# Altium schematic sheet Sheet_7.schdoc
size 444 x 280 mm
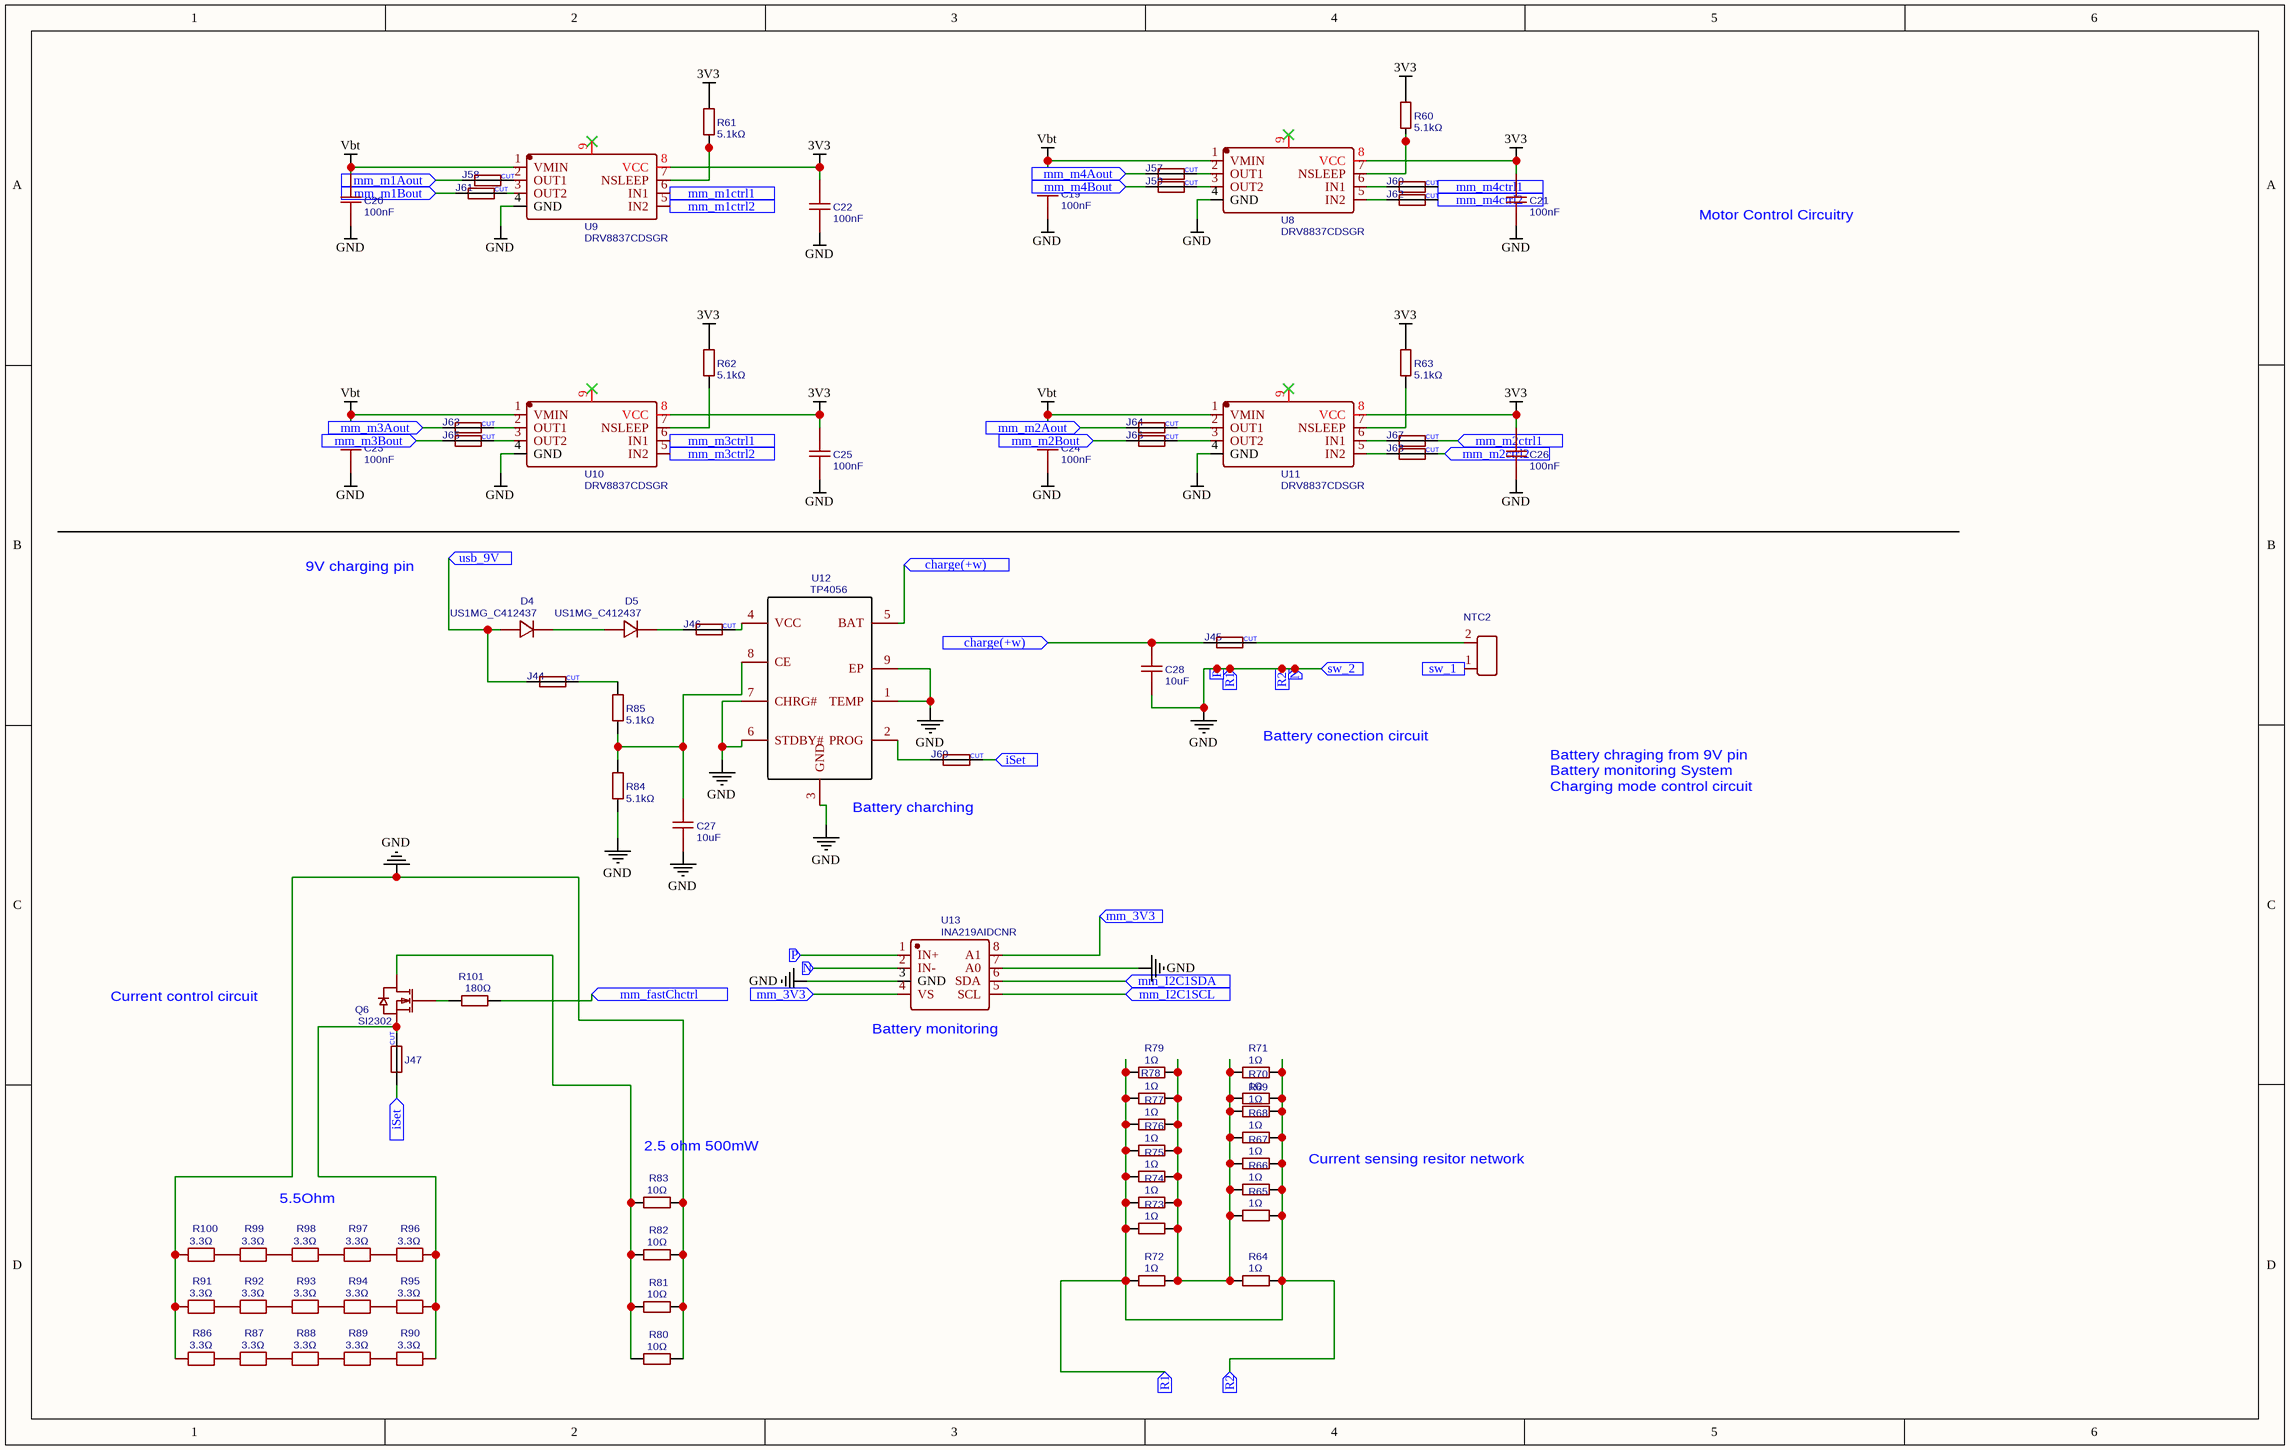
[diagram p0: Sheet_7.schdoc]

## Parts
C19  100nF  [C0805]
C20  100nF  [C0805]
C21  100nF  [C0805]
C22  100nF  [C0805]
C23  100nF  [C0805]
C24  100nF  [C0805]
C25  100nF  [C0805]
C26  100nF  [C0805]
C27  10uF  [C0805]
C28  10uF  [C0805]
D4  US1MG_C412437  [SMA_L4.4-W2.8-LS5.4-RD]
D5  US1MG_C412437  [SMA_L4.4-W2.8-LS5.4-RD]
J44  0603  [JMP-0603-CUTTABLE]  (value not drawn)
J45  0603  [JMP-0603-CUTTABLE]  (value not drawn)
J46  0603  [JMP-0603-CUTTABLE]  (value not drawn)
J47  0603  [JMP-0603-CUTTABLE]  (value not drawn)
J57  0603  [JMP-0603-CUTTABLE]  (value not drawn)
J58  0603  [JMP-0603-CUTTABLE]  (value not drawn)
J59  0603  [JMP-0603-CUTTABLE]  (value not drawn)
J60  0603  [JMP-0603-CUTTABLE]  (value not drawn)
J61  0603  [JMP-0603-CUTTABLE]  (value not drawn)
J62  0603  [JMP-0603-CUTTABLE]  (value not drawn)
J63  0603  [JMP-0603-CUTTABLE]  (value not drawn)
J64  0603  [JMP-0603-CUTTABLE]  (value not drawn)
J65  0603  [JMP-0603-CUTTABLE]  (value not drawn)
J66  0603  [JMP-0603-CUTTABLE]  (value not drawn)
J67  0603  [JMP-0603-CUTTABLE]  (value not drawn)
J68  0603  [JMP-0603-CUTTABLE]  (value not drawn)
J69  0603  [JMP-0603-CUTTABLE]  (value not drawn)
NTC2  NTC/10k  [2PIN_2.54_MM_JST_XHP_JST_CONNECTOR 1]  (value not drawn)
Q6  SI2302  [SOT-23-3_L2.9-W1.3-P1.90-LS2.4-BR]
R60  5.1kΩ  [R0805]
R61  5.1kΩ  [R0805]
R62  5.1kΩ  [R0805]
R63  5.1kΩ  [R0805]
R64  1Ω  [R0402]
R65  1Ω  [R0402]
R66  1Ω  [R0402]
R67  1Ω  [R0402]
R68  1Ω  [R0402]
R69  1Ω  [R0402]
R70  1Ω  [R0402]
R71  1Ω  [R0402]
R72  1Ω  [R0402]
R73  1Ω  [R0402]
R74  1Ω  [R0402]
R75  1Ω  [R0402]
R76  1Ω  [R0402]
R77  1Ω  [R0402]
R78  1Ω  [R0402]
R79  1Ω  [R0402]
R80  10Ω  [R0805_NEW]
R81  10Ω  [R0805_NEW]
R82  10Ω  [R0805_NEW]
R83  10Ω  [R0805_NEW]
R84  5.1kΩ  [R0805]
R85  5.1kΩ  [R0805]
R86  3.3Ω  [R0603]
R87  3.3Ω  [R0603]
R88  3.3Ω  [R0603]
R89  3.3Ω  [R0603]
R90  3.3Ω  [R0603]
R91  3.3Ω  [R0603]
R92  3.3Ω  [R0603]
R93  3.3Ω  [R0603]
R94  3.3Ω  [R0603]
R95  3.3Ω  [R0603]
R96  3.3Ω  [R0603]
R97  3.3Ω  [R0603]
R98  3.3Ω  [R0603]
R99  3.3Ω  [R0603]
R100  3.3Ω  [R0603]
R101  180Ω  [R0805]
U8  DRV8837CDSGR  [WSON-8_L2.0-W2.0-P0.50-TL-EP]
U9  DRV8837CDSGR  [WSON-8_L2.0-W2.0-P0.50-TL-EP]
U10  DRV8837CDSGR  [WSON-8_L2.0-W2.0-P0.50-TL-EP]
U11  DRV8837CDSGR  [WSON-8_L2.0-W2.0-P0.50-TL-EP]
U12  TP4056  [ESOP-8_L4.9-W3.9-P1.27-LS6.0-BL-EP]
U13  INA219AIDCNR  [SOT-23-8_L3.0-W1.7-P0.65-LS2.8-BR]

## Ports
charge(+w) (in), iSet (in), mm_3V3 (in), mm_fastChctrl (in), mm_I2C1SCL (in), mm_I2C1SDA (in), mm_m1Aout (in), mm_m1Bout (in), mm_m1ctrl1 (in), mm_m1ctrl2 (in), mm_m2Aout (in), mm_m2Bout (in), mm_m2ctrl1 (in), mm_m2ctrl2 (in), mm_m3Aout (in), mm_m3Bout (in), mm_m3ctrl1 (in), mm_m3ctrl2 (in), mm_m4Aout (in), mm_m4Bout (in), mm_m4ctrl1 (in), mm_m4ctrl2 (in), N (in), P (in), R1 (in), R2 (in), sw_1 (in), sw_2 (in), usb_9V (in)

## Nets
3V3: C21.1 C22.1 C25.1 C26.1 R60.1 R61.1 R62.1 R63.1 U8.8(VCC) U9.8(VCC) U10.8(VCC) U11.8(VCC)
GND: C19.2 C20.2 C21.2 C22.2 C23.2 C24.2 C25.2 C26.2 C27.2 C28.2 R64.2 R65.2 R66.2 R67.2 R68.2 R69.2 R70.2 R71.2 R72.1 R73.1 R74.1 R75.1 R76.1 R77.1 R78.1 R79.1 R80.2 R81.2 R82.2 R83.2 R84.2 R86.1 R91.1 R100.1 U8.4(GND) U9.4(GND) U10.4(GND) U11.4(GND) U12.1(TEMP) U12.3(GND) U12.6(STDBY#) U12.7(CHRG#) U12.9(EP) U13.1(IN+) U13.2(IN-) U13.3(GND) U13.7(A0) ; port sw_2, port R2, port R1, port N, port P
Vbt: C19.1 C20.1 C23.1 C24.1 U8.1(VMIN) U9.1(VMIN) U10.1(VMIN) U11.1(VMIN)
charge(+w): C28.1 J45.2 U12.5(BAT) ; port charge(+w)
iSet: J47.2 J69.1 ; port iSet
mm_3V3: U13.4(VS) U13.8(A1) ; port mm_3V3
mm_fastChctrl: R101.2 ; port mm_fastChctrl
mm_I2C1SCL: U13.5(SCL) ; port mm_I2C1SCL
mm_I2C1SDA: U13.6(SDA) ; port mm_I2C1SDA
mm_m1Aout: J58.2 ; port mm_m1Aout
mm_m1Bout: J61.2 ; port mm_m1Bout
mm_m1ctrl1: U9.6(IN1) ; port mm_m1ctrl1
mm_m1ctrl2: U9.5(IN2) ; port mm_m1ctrl2
mm_m2Aout: J64.2 ; port mm_m2Aout
mm_m2Bout: J66.2 ; port mm_m2Bout
mm_m2ctrl1: J67.1 ; port mm_m2ctrl1
mm_m2ctrl2: J68.1 ; port mm_m2ctrl2
mm_m3Aout: J63.2 ; port mm_m3Aout
mm_m3Bout: J65.2 ; port mm_m3Bout
mm_m3ctrl1: U10.6(IN1) ; port mm_m3ctrl1
mm_m3ctrl2: U10.5(IN2) ; port mm_m3ctrl2
mm_m4Aout: J57.2 ; port mm_m4Aout
mm_m4Bout: J59.2 ; port mm_m4Bout
mm_m4ctrl1: J60.1 ; port mm_m4ctrl1
mm_m4ctrl2: J62.1 ; port mm_m4ctrl2
sw_1: NTC2.1 ; port sw_1
usb_9V: D4.2(A) J44.2 ; port usb_9V
NetC27_1: C27.1 R84.1 R85.2 U12.8(CE)
NetD4_1: D4.1(C) D5.2(A)
NetD5_1: D5.1(C) J46.2
NetJ44_1: J44.1 R85.1
NetJ45_1: J45.1 NTC2.2
NetJ46_1: J46.1 U12.4(VCC)
NetJ47_1: J47.1 Q6.2(S) R90.2 R95.2 R96.2
NetJ57_1: J57.1 U8.2(OUT1)
NetJ58_1: J58.1 U9.2(OUT1)
NetJ59_1: J59.1 U8.3(OUT2)
NetJ60_2: J60.2 U8.6(IN1)
NetJ61_1: J61.1 U9.3(OUT2)
NetJ62_2: J62.2 U8.5(IN2)
NetJ63_1: J63.1 U10.2(OUT1)
NetJ64_1: J64.1 U11.2(OUT1)
NetJ65_1: J65.1 U10.3(OUT2)
NetJ66_1: J66.1 U11.3(OUT2)
NetJ67_2: J67.2 U11.6(IN1)
NetJ68_2: J68.2 U11.5(IN2)
NetJ69_2: J69.2 U12.2(PROG)
NetQ6_1: Q6.1(G) R101.1
NetQ6_3: Q6.3(D) R80.1 R81.1 R82.1 R83.1
NetR60_2: R60.2 U8.7(NSLEEP)
NetR61_2: R61.2 U9.7(NSLEEP)
NetR62_2: R62.2 U10.7(NSLEEP)
NetR63_2: R63.2 U11.7(NSLEEP)
NetR64_1: R64.1 R65.1 R66.1 R67.1 R68.1 R69.1 R70.1 R71.1 R72.2 R73.2 R74.2 R75.2 R76.2 R77.2 R78.2 R79.2
NetR86_2: R86.2 R87.1
NetR87_2: R87.2 R88.1
NetR88_2: R88.2 R89.1
NetR89_2: R89.2 R90.1
NetR91_2: R91.2 R92.1
NetR92_2: R92.2 R93.1
NetR93_2: R93.2 R94.1
NetR94_2: R94.2 R95.1
NetR96_1: R96.1 R97.2
NetR97_1: R97.1 R98.2
NetR98_1: R98.1 R99.2
NetR99_1: R99.1 R100.2

Not connected (* = marked no-connect by the designer): U8 9(PAD)*; U9 9(PAD)*; U10 9(PAD)*; U11 9(PAD)*

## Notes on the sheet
- Motor Control Circuitry
- 9V charging pin
- Battery conection circuit
- Battery chraging from 9V pin
  Battery monitoring System
  Charging mode control circuit
- (near U12) Battery charching
- Current control circuit
- (near U13) Battery monitoring
- 5.5Ohm
- (near R83) 2.5 ohm 500mW
- Current sensing resitor network

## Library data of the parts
C19-C26 = 100nF: Manufacturer Part: CC0805KRX7R9BB104; Manufacturer: YAGEO(国巨); nameAlias: Value
C27 C28 = 10uF: Manufacturer: SAMSUNG(三星); nameAlias: Value
D4 D5 = US1MG_C412437: Manufacturer: MDD(辰达半导体); Manufacturer Part: US1M; Contributor: LCSC
J44-J47 J57-J69 = 0603: Manufacturer: Tim Hosking; Contributor: MisterJan
NTC2 = NTC/10k: Contributor: OpenGreenEnergy
Q6 = SI2302: Manufacturer: MDD(辰达半导体); Contributor: LCSC
R60-R63 R84 R85 = 5.1kΩ: Manufacturer: UNI-ROYAL(厚声); nameAlias: Value
R64-R79 = 1Ω: Manufacturer: UNI-ROYAL(厚声); Manufacturer Part: 0402WGF100KTCE; nameAlias: Value
R80-R83 = 10Ω: Manufacturer: UNI-ROYAL(厚声); Manufacturer Part: 0805W8F100JT5E; nameAlias: Value
R86-R100 = 3.3Ω: Manufacturer: FOJAN(富捷); Manufacturer Part: FRC0603F3R30TS; Contributor: lcsc; nameAlias: Value
R101 = 180Ω: Manufacturer: UNI-ROYAL(厚声); nameAlias: Value
U8-U11 = DRV8837CDSGR: Manufacturer: TI(德州仪器); Contributor: LCSC
U12 = TP4056: Manufacturer: TOPPOWER(南京拓微); Manufacturer Part: TP4056-42-ESOP8; Contributor: Guest
U13 = INA219AIDCNR: Manufacturer: TI(德州仪器); Contributor: LCSC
